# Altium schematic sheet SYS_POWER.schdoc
size 297 x 209 mm; Symbol: Drawing-Symbol_A4; Company: 嘉立创EDA; Version: V1.0; Page Size: A4; @Project Name: 西柚在学EtherCAT; @Update Date: 2026-07-29; @Create Date: 2026-07-29; Device: Drawing-Symbol_A4; @Board Name: HPM5E3YIVK1; @Page Name: P3; @Create Time: 01:19:14; @Page Count: 3; @Page No: 3; @Schematic Name: HPM5E3YIVK1; @Update Time: 01:19:14; @Assembly Variant: Basic; Border: 1; Title Block Position: 3; Size: A4; Width: 1170; Height: 825; Region Start: 1; X Region Count: 6; Y Region Count: 4; Blade Width: 10
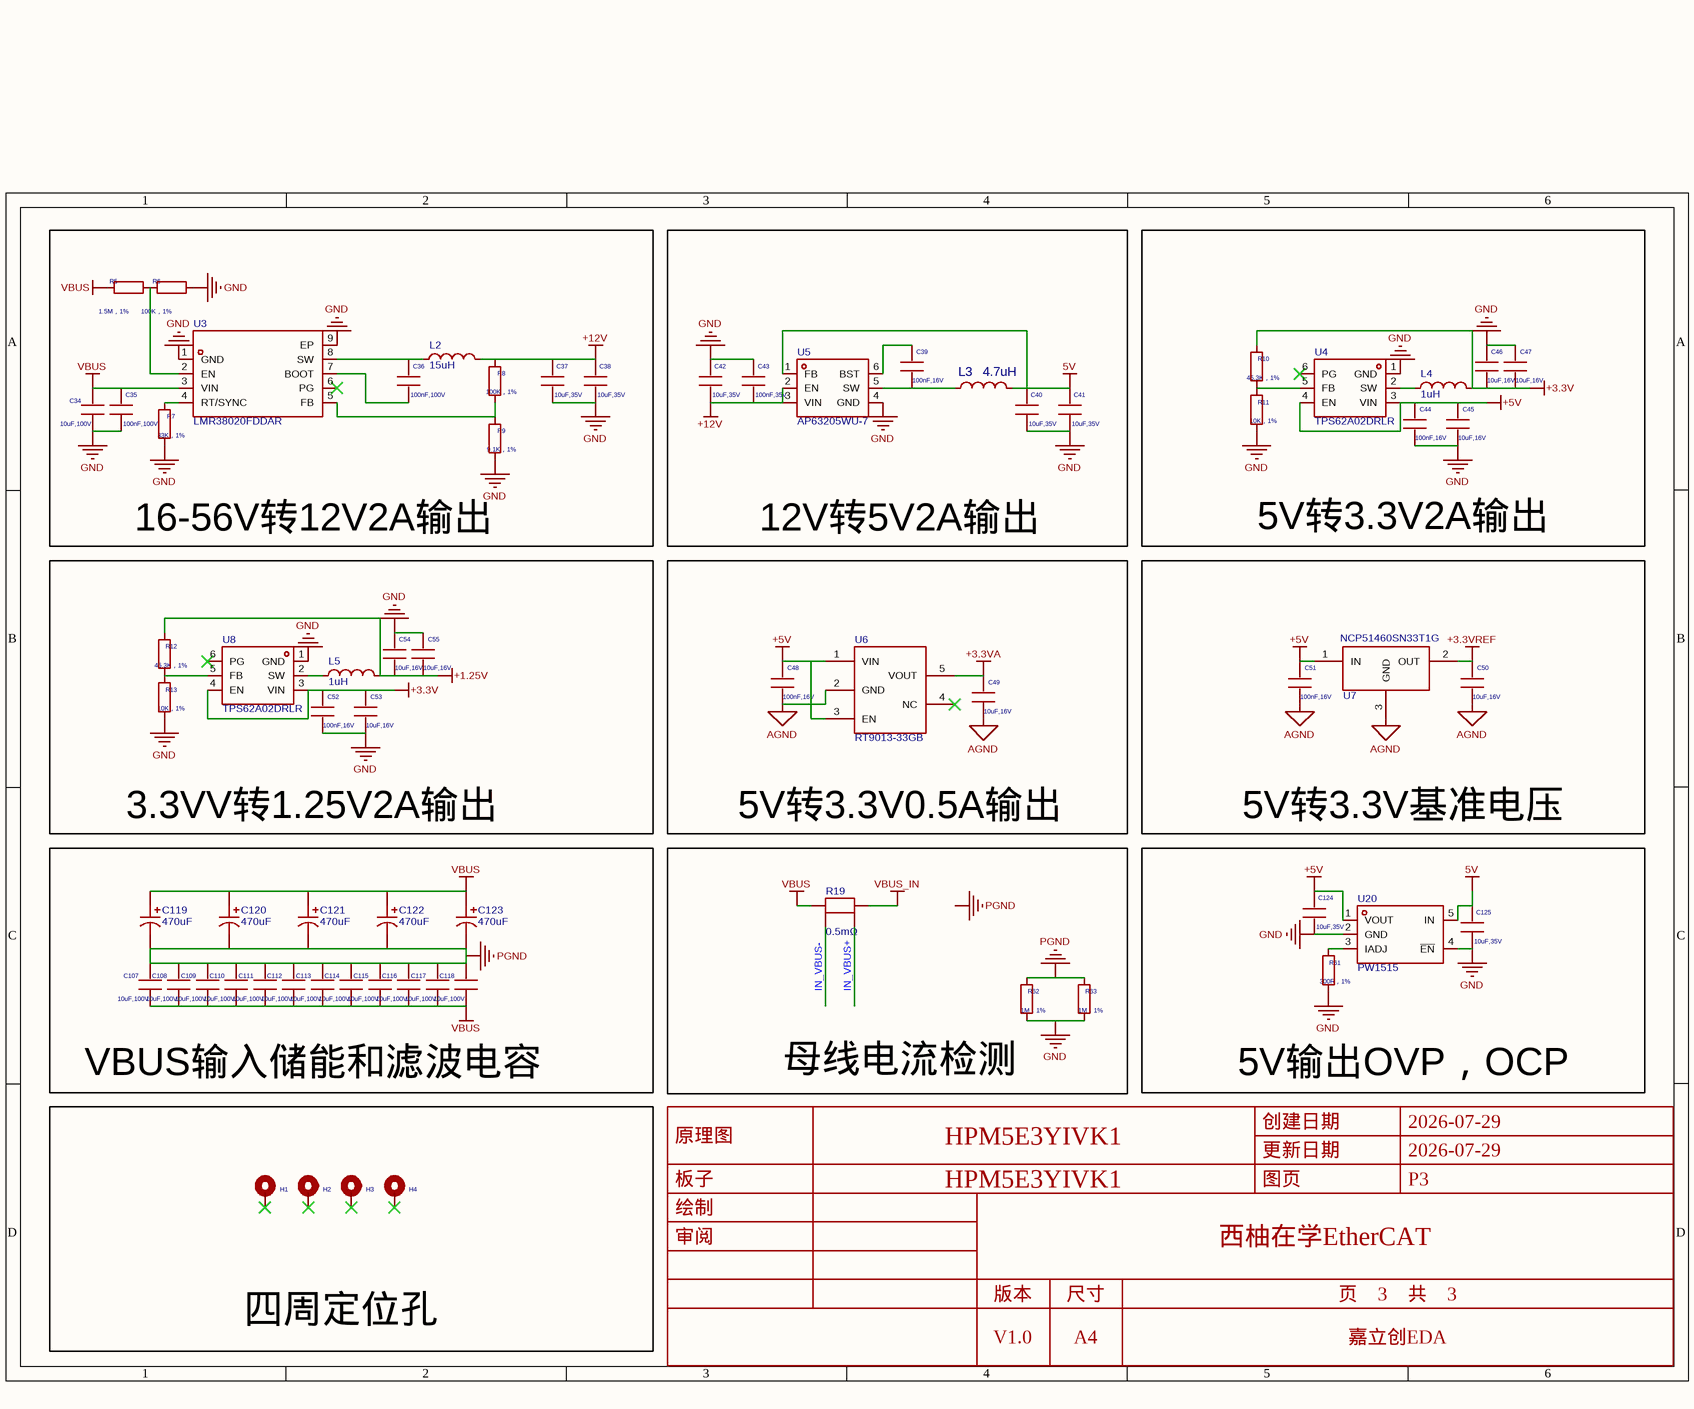
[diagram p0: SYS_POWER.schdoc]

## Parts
C34  value 10uF,100V  [03_HPM_Capacitance:C_1206_3216Metric]
C35  value 100nF,100V  [03_HPM_Capacitance:C_0603_1608Metric]
C36  value 100nF,100V  [03_HPM_Capacitance:C_0603_1608Metric]
C37  value 10uF,35V  [03_HPM_Capacitance:C_0603_1608Metric]
C38  value 10uF,35V  [03_HPM_Capacitance:C_0603_1608Metric]
C39  value 100nF,16V  [03_HPM_Capacitance:C_0402_1005Metric]
C40  value 10uF,35V  [03_HPM_Capacitance:C_0603_1608Metric]
C41  value 10uF,35V  [03_HPM_Capacitance:C_0603_1608Metric]
C42  value 10uF,35V  [03_HPM_Capacitance:C_0603_1608Metric]
C43  value 100nF,35V  [03_HPM_Capacitance:C_0603_1608Metric]
C44  value 100nF,16V  [03_HPM_Capacitance:C_0402_1005Metric]
C45  value 10uF,16V  [03_HPM_Capacitance:C_0402_1005Metric]
C46  value 10uF,16V  [03_HPM_Capacitance:C_0402_1005Metric]
C47  value 10uF,16V  [03_HPM_Capacitance:C_0402_1005Metric]
C48  value 100nF,16V  [03_HPM_Capacitance:C_0402_1005Metric]
C49  value 10uF,16V  [03_HPM_Capacitance:C_0402_1005Metric]
C50  value 10uF,16V  [03_HPM_Capacitance:C_0402_1005Metric]
C51  value 100nF,16V  [03_HPM_Capacitance:C_0402_1005Metric]
C52  value 100nF,16V  [03_HPM_Capacitance:C_0402_1005Metric]
C53  value 10uF,16V  [03_HPM_Capacitance:C_0402_1005Metric]
C54  value 10uF,16V  [03_HPM_Capacitance:C_0402_1005Metric]
C55  value 10uF,16V  [03_HPM_Capacitance:C_0402_1005Metric]
C107  value 10uF,100V  [03_HPM_Capacitance:C_1206_3216Metric]
C108  value 10uF,100V  [03_HPM_Capacitance:C_1206_3216Metric]
C109  value 10uF,100V  [03_HPM_Capacitance:C_1206_3216Metric]
C110  value 10uF,100V  [03_HPM_Capacitance:C_1206_3216Metric]
C111  value 10uF,100V  [03_HPM_Capacitance:C_1206_3216Metric]
C112  value 10uF,100V  [03_HPM_Capacitance:C_1206_3216Metric]
C113  value 10uF,100V  [03_HPM_Capacitance:C_1206_3216Metric]
C114  value 10uF,100V  [03_HPM_Capacitance:C_1206_3216Metric]
C115  value 10uF,100V  [03_HPM_Capacitance:C_1206_3216Metric]
C116  value 10uF,100V  [03_HPM_Capacitance:C_1206_3216Metric]
C117  value 10uF,100V  [03_HPM_Capacitance:C_1206_3216Metric]
C118  value 10uF,100V  [03_HPM_Capacitance:C_1206_3216Metric]
C119  470uF  [CAP-TH_BD8.0-P3.50-D0.6-FD]
C120  470uF  [CAP-TH_BD8.0-P3.50-D0.6-FD]
C121  470uF  [CAP-TH_BD8.0-P3.50-D0.6-FD]
C122  470uF  [CAP-TH_BD8.0-P3.50-D0.6-FD]
C123  470uF  [CAP-TH_BD8.0-P3.50-D0.6-FD]
C124  value 10uF,35V  [03_HPM_Capacitance:C_0603_1608Metric]
C125  value 10uF,35V  [03_HPM_Capacitance:C_0603_1608Metric]
H1  01-HPM-Peripheral_MountingHole_Pad  [01_HPM_Peripheral:FIX1]  (value not drawn)
H2  01-HPM-Peripheral_MountingHole_Pad  [01_HPM_Peripheral:FIX1]  (value not drawn)
H3  01-HPM-Peripheral_MountingHole_Pad  [01_HPM_Peripheral:FIX1]  (value not drawn)
H4  01-HPM-Peripheral_MountingHole_Pad  [01_HPM_Peripheral:FIX1]  (value not drawn)
L2  15uH  [IND-SMD_L4.6-W4.2_SMMS0420]
L3  4.7uH  [IND-SMD_L2.5-W2.0-VLS252012CX-150M]
L4  1uH  [IND-SMD_L2.5-W2.0-VLS252012CX-150M]
L5  1uH  [IND-SMD_L2.5-W2.0-VLS252012CX-150M]
R5  value 1.5M，1%  [02_HPM_Resistor:R_0402_1005Metric]
R6  value 100K，1%  [02_HPM_Resistor:R_0402_1005Metric]
R7  value 33K，1%  [02_HPM_Resistor:R_0402_1005Metric]
R8  value 100K，1%  [02_HPM_Resistor:R_0402_1005Metric]
R9  value 9.1K，1%  [02_HPM_Resistor:R_0402_1005Metric]
R10  value 45.3K，1%  [02_HPM_Resistor:R_0402_1005Metric]
R11  value 10K，1%  [02_HPM_Resistor:R_0402_1005Metric]
R12  value 45.3K，1%  [02_HPM_Resistor:R_0402_1005Metric]
R13  value 10K，1%  [02_HPM_Resistor:R_0402_1005Metric]
R19  0.5mΩ  [RES-SMD_4P-L3.0-W3.8_HOBB1216]
R61  value 300R，1%  [02_HPM_Resistor:R_0402_1005Metric]
R62  value 1M，1%  [02_HPM_Resistor:R_1206_3216Metric]
R63  value 1M，1%  [02_HPM_Resistor:R_1206_3216Metric]
U3  LMR38020FDDAR  [ESOP-8_L4.9-W3.9-P1.27-LS6.0-BL-EP-1]
U4  TPS62A02DRLR  [SOT-563_L1.6-W1.2-P0.50-LS1.6-TL]
U5  AP63205WU-7  [TSOT-23-6_L2.9-W1.6-P0.95-LS2.8-BL]
U6  RT9013-33GB  [SOT-23-5_L3.0-W1.7-P0.95-LS2.8-BL]
U7  NCP51460SN33T1G  [SOT-23_L2.9-W1.3-P1.90-LS2.4-BR]
U8  TPS62A02DRLR  [SOT-563_L1.6-W1.2-P0.50-LS1.6-TL]
U20  (no value)  [SOT-23-5_L2.9-W1.7-P0.95-LS2.8-BL]

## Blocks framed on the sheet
16-56V转12V2A输出: C34-C38 L2 R5-R9 U3
12V转5V2A输出: C39-C43 L3 U5
5V转3.3V2A输出: C44-C47 L4 R10 R11 U4
5V转3.3V基准电压: C50 C51 U7
四周定位孔: H1-H4

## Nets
5V: C40.1 C41.1 C125.1 L3.2 U5.1(FB) U20.5(IN)
+1.25V: C54.2 C55.2 L5.2 R12.1
+3.3V: C46.2 C47.2 C52.1 C53.1 L4.2 R10.1 U8.3(VIN) U8.4(EN)
+3.3VA: C49.1 U6.5(VOUT)
+3.3VREF: C50.1 U7.2(OUT)
+5V: C44.1 C45.1 C48.1 C51.1 C124.1 U4.3(VIN) U4.4(EN) U6.1(VIN) U6.3(EN) U7.1(IN) U20.1(VOUT)
+12V: C37.1 C38.1 C42.2 C43.2 L2.2 R8.2 U5.2(EN) U5.3(VIN)
AGND: C48.2 C49.2 C50.2 C51.2 U6.2(GND) U7.3(GND)
GND: C34.2 C35.2 C37.2 C38.2 C40.2 C41.2 C42.1 C43.1 C44.2 C45.2 C46.1 C47.1 C52.2 C53.2 C54.1 C55.1 C124.2 C125.2 R6.2 R7.2 R9.1 R11.1 R13.1 R61.2 R62.2 R63.2 U3.1(GND) U3.9(EP) U4.1(GND) U5.4(GND) U8.1(GND) U20.2(GND) U20.4(~{EN})
PGND: C107.1 C108.1 C109.1 C110.1 C111.1 C112.1 C113.1 C114.1 C115.1 C116.1 C117.1 C118.1 C119.2 C120.2 C121.2 C122.2 C123.2 R62.1 R63.1
VBUS: C34.1 C35.1 C107.2 C108.2 C109.2 C110.2 C111.2 C112.2 C113.2 C114.2 C115.2 C116.2 C117.2 C118.2 C119.1 C120.1 C121.1 C122.1 C123.1 R5.1 R19.2 U3.3(VIN)
VBUS_IN: R19.1
IN_VBUS+: R19.3
IN_VBUS-: R19.4
NetC36_1: C36.1 L2.1 U3.8(SW)
NetC36_2: C36.2 U3.7(BOOT)
NetC39_1: C39.1 U5.6(BST)
NetC39_2: C39.2 L3.1 U5.5(SW)
NetL4_1: L4.1 U4.2(SW)
NetL5_1: L5.1 U8.2(SW)
NetR5_2: R5.2 R6.1 U3.2(EN)
NetR7_1: R7.1 U3.4(RT/SYNC)
NetR8_1: R8.1 R9.2 U3.5(FB)
NetR10_2: R10.2 R11.2 U4.5(FB)
NetR12_2: R12.2 R13.2 U8.5(FB)
NetR61_1: R61.1 U20.3(IADJ)

Not connected (* = marked no-connect by the designer): H1 1*; H2 1*; H3 1*; H4 1*; U3 6(PG)*; U4 6(PG)*; U6 4(NC)*; U8 6(PG)*

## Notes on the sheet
- 3.3VV转1.25V2A输出
- 5V转3.3V0.5A输出
- VBUS输入储能和滤波电容
- 母线电流检测
- 5V输出OVP，OCP
- Labels drawn without touching a wire or pin: PGND

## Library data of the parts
C34 = 电容1206: Model: 1206B102K202NT; Company: FH(风华); AddInBom: yes; ki_keywords: cap capacitor; ki_description: 1206; ki_fp_filters: C_*; UniqueId: gge1041; ID: $4I70; ModelId: e4be705b945545a48e666415e3682bd80819f05c4eef4c71ace90d822a990e87; ModelName: C1206_L3.2-W1.6-H1.3; ModelTransform: 125.98400187730789,62.992000938653945,51.1809981226921,0,0,0,0,0,0
C35 = 电容0603: Model: CL10A226MP8NUNE; Company: SAMSUNG(三星); AddInBom: yes; ki_keywords: cap capacitor; ki_description: 0603; ki_fp_filters: C_*; UniqueId: gge1042; ID: $1I15; ModelId: fca5be93b99f4b5a9a2fd372d58c31d90819f05c4eef4c71ace90d822a990e87; ModelName: C0603; ModelTransform: 62.992000938653945,31.496000469326972,31.496000469326972,0,0,0,0,0,0
C36 = 电容0603: Model: CL10A226MP8NUNE; Company: SAMSUNG(三星); AddInBom: yes; ki_keywords: cap capacitor; ki_description: 0603; ki_fp_filters: C_*; UniqueId: b3e980a047527b8f_28; ID: $1I15; ModelId: fca5be93b99f4b5a9a2fd372d58c31d90819f05c4eef4c71ace90d822a990e87; ModelName: C0603; ModelTransform: 62.992000938653945,31.496000469326972,31.496000469326972,0,0,0,0,0,0
C37 = 电容0603: Model: CL10A226MP8NUNE; Company: SAMSUNG(三星); AddInBom: yes; ki_keywords: cap capacitor; ki_description: 0603; ki_fp_filters: C_*; UniqueId: b3e980a047527b8f_26; ID: $1I15; ModelId: fca5be93b99f4b5a9a2fd372d58c31d90819f05c4eef4c71ace90d822a990e87; ModelName: C0603; ModelTransform: 62.992000938653945,31.496000469326972,31.496000469326972,0,0,0,0,0,0
C38 = 电容0603: Model: CL10A226MP8NUNE; Company: SAMSUNG(三星); AddInBom: yes; ki_keywords: cap capacitor; ki_description: 0603; ki_fp_filters: C_*; UniqueId: b3e980a047527b8f_27; ID: $1I15; ModelId: fca5be93b99f4b5a9a2fd372d58c31d90819f05c4eef4c71ace90d822a990e87; ModelName: C0603; ModelTransform: 62.992000938653945,31.496000469326972,31.496000469326972,0,0,0,0,0,0
C39 = 电容0402: Model: CL05B104KO5NNNC; Company: SAMSUNG(三星); ki_keywords: cap capacitor; ki_description: 0402; ki_fp_filters: C_*; ID: $1I27; 3D Model: 222a10e09e6e477a9f85628e277082cb0819f05c4eef4c71ace90d822a990e87; 3D Model Transform: 39.37,19.685,19.685,0,0,0,0,0,0; AddInBom: yes; UniqueId: gge1020; ModelName: C0402
C40 = 电容0603: Model: CL10A226MP8NUNE; Company: SAMSUNG(三星); AddInBom: yes; ki_keywords: cap capacitor; ki_description: 0603; ki_fp_filters: C_*; UniqueId: b3e980a047527b8f_29; ID: $1I15; ModelId: fca5be93b99f4b5a9a2fd372d58c31d90819f05c4eef4c71ace90d822a990e87; ModelName: C0603; ModelTransform: 62.992000938653945,31.496000469326972,31.496000469326972,0,0,0,0,0,0
C41 = 电容0603: Model: CL10A226MP8NUNE; Company: SAMSUNG(三星); AddInBom: yes; ki_keywords: cap capacitor; ki_description: 0603; ki_fp_filters: C_*; UniqueId: b3e980a047527b8f_30; ID: $1I15; ModelId: fca5be93b99f4b5a9a2fd372d58c31d90819f05c4eef4c71ace90d822a990e87; ModelName: C0603; ModelTransform: 62.992000938653945,31.496000469326972,31.496000469326972,0,0,0,0,0,0
C42 = 电容0603: Model: CL10A226MP8NUNE; Company: SAMSUNG(三星); AddInBom: yes; ki_keywords: cap capacitor; ki_description: 0603; ki_fp_filters: C_*; UniqueId: b3e980a047527b8f_31; ID: $1I15; ModelId: fca5be93b99f4b5a9a2fd372d58c31d90819f05c4eef4c71ace90d822a990e87; ModelName: C0603; ModelTransform: 62.992000938653945,31.496000469326972,31.496000469326972,0,0,0,0,0,0
C43 = 电容0603: Model: CL10A226MP8NUNE; Company: SAMSUNG(三星); AddInBom: yes; ki_keywords: cap capacitor; ki_description: 0603; ki_fp_filters: C_*; UniqueId: b3e980a047527b8f_32; ID: $1I15; ModelId: fca5be93b99f4b5a9a2fd372d58c31d90819f05c4eef4c71ace90d822a990e87; ModelName: C0603; ModelTransform: 62.992000938653945,31.496000469326972,31.496000469326972,0,0,0,0,0,0
C44 = 电容0402: Model: CL05B104KO5NNNC; Company: SAMSUNG(三星); ki_keywords: cap capacitor; ki_description: 0402; ki_fp_filters: C_*; ID: $1I27; 3D Model: 222a10e09e6e477a9f85628e277082cb0819f05c4eef4c71ace90d822a990e87; 3D Model Transform: 39.37,19.685,19.685,0,0,0,0,0,0; AddInBom: yes; UniqueId: gge1023; ModelName: C0402
C45 = 电容0402: Model: CL05B104KO5NNNC; Company: SAMSUNG(三星); ki_keywords: cap capacitor; ki_description: 0402; ki_fp_filters: C_*; ID: $1I27; 3D Model: 222a10e09e6e477a9f85628e277082cb0819f05c4eef4c71ace90d822a990e87; 3D Model Transform: 39.37,19.685,19.685,0,0,0,0,0,0; AddInBom: yes; UniqueId: gge1024; ModelName: C0402
C46 = 电容0402: Model: CL05B104KO5NNNC; Company: SAMSUNG(三星); ki_keywords: cap capacitor; ki_description: 0402; ki_fp_filters: C_*; ID: $1I27; 3D Model: 222a10e09e6e477a9f85628e277082cb0819f05c4eef4c71ace90d822a990e87; 3D Model Transform: 39.37,19.685,19.685,0,0,0,0,0,0; AddInBom: yes; UniqueId: b3e980a047527b8f_33; ModelName: C0402
C47 = 电容0402: Model: CL05B104KO5NNNC; Company: SAMSUNG(三星); ki_keywords: cap capacitor; ki_description: 0402; ki_fp_filters: C_*; ID: $1I27; 3D Model: 222a10e09e6e477a9f85628e277082cb0819f05c4eef4c71ace90d822a990e87; 3D Model Transform: 39.37,19.685,19.685,0,0,0,0,0,0; AddInBom: yes; UniqueId: b3e980a047527b8f_34; ModelName: C0402
C48 = 电容0402: Model: CL05B104KO5NNNC; Company: SAMSUNG(三星); ki_keywords: cap capacitor; ki_description: 0402; ki_fp_filters: C_*; ID: $1I27; 3D Model: 222a10e09e6e477a9f85628e277082cb0819f05c4eef4c71ace90d822a990e87; 3D Model Transform: 39.37,19.685,19.685,0,0,0,0,0,0; AddInBom: yes; UniqueId: b3e980a047527b8f_35; ModelName: C0402
C49 = 电容0402: Model: CL05B104KO5NNNC; Company: SAMSUNG(三星); ki_keywords: cap capacitor; ki_description: 0402; ki_fp_filters: C_*; ID: $1I27; 3D Model: 222a10e09e6e477a9f85628e277082cb0819f05c4eef4c71ace90d822a990e87; 3D Model Transform: 39.37,19.685,19.685,0,0,0,0,0,0; AddInBom: yes; UniqueId: b3e980a047527b8f_36; ModelName: C0402
C50 = 电容0402: Model: CL05B104KO5NNNC; Company: SAMSUNG(三星); ki_keywords: cap capacitor; ki_description: 0402; ki_fp_filters: C_*; ID: $1I27; 3D Model: 222a10e09e6e477a9f85628e277082cb0819f05c4eef4c71ace90d822a990e87; 3D Model Transform: 39.37,19.685,19.685,0,0,0,0,0,0; AddInBom: yes; UniqueId: b3e980a047527b8f_37; ModelName: C0402
C51 = 电容0402: Model: CL05B104KO5NNNC; Company: SAMSUNG(三星); ki_keywords: cap capacitor; ki_description: 0402; ki_fp_filters: C_*; ID: $1I27; 3D Model: 222a10e09e6e477a9f85628e277082cb0819f05c4eef4c71ace90d822a990e87; 3D Model Transform: 39.37,19.685,19.685,0,0,0,0,0,0; AddInBom: yes; UniqueId: b3e980a047527b8f_38; ModelName: C0402
C52 = 电容0402: Model: CL05B104KO5NNNC; Company: SAMSUNG(三星); ki_keywords: cap capacitor; ki_description: 0402; ki_fp_filters: C_*; ID: $1I27; 3D Model: 222a10e09e6e477a9f85628e277082cb0819f05c4eef4c71ace90d822a990e87; 3D Model Transform: 39.37,19.685,19.685,0,0,0,0,0,0; AddInBom: yes; UniqueId: gge1023_0; ModelName: C0402
C53 = 电容0402: Model: CL05B104KO5NNNC; Company: SAMSUNG(三星); ki_keywords: cap capacitor; ki_description: 0402; ki_fp_filters: C_*; ID: $1I27; 3D Model: 222a10e09e6e477a9f85628e277082cb0819f05c4eef4c71ace90d822a990e87; 3D Model Transform: 39.37,19.685,19.685,0,0,0,0,0,0; AddInBom: yes; UniqueId: gge1024_0; ModelName: C0402
C54 = 电容0402: Model: CL05B104KO5NNNC; Company: SAMSUNG(三星); ki_keywords: cap capacitor; ki_description: 0402; ki_fp_filters: C_*; ID: $1I27; 3D Model: 222a10e09e6e477a9f85628e277082cb0819f05c4eef4c71ace90d822a990e87; 3D Model Transform: 39.37,19.685,19.685,0,0,0,0,0,0; AddInBom: yes; UniqueId: b3e980a047527b8f_39; ModelName: C0402
C55 = 电容0402: Model: CL05B104KO5NNNC; Company: SAMSUNG(三星); ki_keywords: cap capacitor; ki_description: 0402; ki_fp_filters: C_*; ID: $1I27; 3D Model: 222a10e09e6e477a9f85628e277082cb0819f05c4eef4c71ace90d822a990e87; 3D Model Transform: 39.37,19.685,19.685,0,0,0,0,0,0; AddInBom: yes; UniqueId: b3e980a047527b8f_40; ModelName: C0402
C107 = 电容1206: Model: 1206B102K202NT; Company: FH(风华); ki_keywords: cap capacitor; ki_description: 1206; ki_fp_filters: C_*; ID: $4I70; 3D Model: e4be705b945545a48e666415e3682bd80819f05c4eef4c71ace90d822a990e87; 3D Model Transform: 125.98400187730789,62.992000938653945,51.1809981226921,0,0,0,0,0,0; AddInBom: yes; UniqueId: gge1041_0; ModelName: C1206_L3.2-W1.6-H1.3
C108 = 电容1206: Model: 1206B102K202NT; Company: FH(风华); ki_keywords: cap capacitor; ki_description: 1206; ki_fp_filters: C_*; ID: $4I70; 3D Model: e4be705b945545a48e666415e3682bd80819f05c4eef4c71ace90d822a990e87; 3D Model Transform: 125.98400187730789,62.992000938653945,51.1809981226921,0,0,0,0,0,0; AddInBom: yes; UniqueId: gge1041_1; ModelName: C1206_L3.2-W1.6-H1.3
C109 = 电容1206: Model: 1206B102K202NT; Company: FH(风华); ki_keywords: cap capacitor; ki_description: 1206; ki_fp_filters: C_*; ID: $4I70; 3D Model: e4be705b945545a48e666415e3682bd80819f05c4eef4c71ace90d822a990e87; 3D Model Transform: 125.98400187730789,62.992000938653945,51.1809981226921,0,0,0,0,0,0; AddInBom: yes; UniqueId: gge1041_2; ModelName: C1206_L3.2-W1.6-H1.3
C110 = 电容1206: Model: 1206B102K202NT; Company: FH(风华); ki_keywords: cap capacitor; ki_description: 1206; ki_fp_filters: C_*; ID: $4I70; 3D Model: e4be705b945545a48e666415e3682bd80819f05c4eef4c71ace90d822a990e87; 3D Model Transform: 125.98400187730789,62.992000938653945,51.1809981226921,0,0,0,0,0,0; AddInBom: yes; UniqueId: gge1041_3; ModelName: C1206_L3.2-W1.6-H1.3
C111 = 电容1206: Model: 1206B102K202NT; Company: FH(风华); ki_keywords: cap capacitor; ki_description: 1206; ki_fp_filters: C_*; ID: $4I70; 3D Model: e4be705b945545a48e666415e3682bd80819f05c4eef4c71ace90d822a990e87; 3D Model Transform: 125.98400187730789,62.992000938653945,51.1809981226921,0,0,0,0,0,0; AddInBom: yes; UniqueId: gge1041_8; ModelName: C1206_L3.2-W1.6-H1.3
C112 = 电容1206: Model: 1206B102K202NT; Company: FH(风华); ki_keywords: cap capacitor; ki_description: 1206; ki_fp_filters: C_*; ID: $4I70; 3D Model: e4be705b945545a48e666415e3682bd80819f05c4eef4c71ace90d822a990e87; 3D Model Transform: 125.98400187730789,62.992000938653945,51.1809981226921,0,0,0,0,0,0; AddInBom: yes; UniqueId: gge1041_9; ModelName: C1206_L3.2-W1.6-H1.3
C113 = 电容1206: Model: 1206B102K202NT; Company: FH(风华); ki_keywords: cap capacitor; ki_description: 1206; ki_fp_filters: C_*; ID: $4I70; 3D Model: e4be705b945545a48e666415e3682bd80819f05c4eef4c71ace90d822a990e87; 3D Model Transform: 125.98400187730789,62.992000938653945,51.1809981226921,0,0,0,0,0,0; AddInBom: yes; UniqueId: gge1041_12; ModelName: C1206_L3.2-W1.6-H1.3
C114 = 电容1206: Model: 1206B102K202NT; Company: FH(风华); ki_keywords: cap capacitor; ki_description: 1206; ki_fp_filters: C_*; ID: $4I70; 3D Model: e4be705b945545a48e666415e3682bd80819f05c4eef4c71ace90d822a990e87; 3D Model Transform: 125.98400187730789,62.992000938653945,51.1809981226921,0,0,0,0,0,0; AddInBom: yes; UniqueId: gge1041_7; ModelName: C1206_L3.2-W1.6-H1.3
C115 = 电容1206: Model: 1206B102K202NT; Company: FH(风华); ki_keywords: cap capacitor; ki_description: 1206; ki_fp_filters: C_*; ID: $4I70; 3D Model: e4be705b945545a48e666415e3682bd80819f05c4eef4c71ace90d822a990e87; 3D Model Transform: 125.98400187730789,62.992000938653945,51.1809981226921,0,0,0,0,0,0; AddInBom: yes; UniqueId: gge1041_4; ModelName: C1206_L3.2-W1.6-H1.3
C116 = 电容1206: Model: 1206B102K202NT; Company: FH(风华); ki_keywords: cap capacitor; ki_description: 1206; ki_fp_filters: C_*; ID: $4I70; 3D Model: e4be705b945545a48e666415e3682bd80819f05c4eef4c71ace90d822a990e87; 3D Model Transform: 125.98400187730789,62.992000938653945,51.1809981226921,0,0,0,0,0,0; AddInBom: yes; UniqueId: gge1041_5; ModelName: C1206_L3.2-W1.6-H1.3
C117 = 电容1206: Model: 1206B102K202NT; Company: FH(风华); ki_keywords: cap capacitor; ki_description: 1206; ki_fp_filters: C_*; ID: $4I70; 3D Model: e4be705b945545a48e666415e3682bd80819f05c4eef4c71ace90d822a990e87; 3D Model Transform: 125.98400187730789,62.992000938653945,51.1809981226921,0,0,0,0,0,0; AddInBom: yes; UniqueId: gge1041_10; ModelName: C1206_L3.2-W1.6-H1.3
C118 = 电容1206: Model: 1206B102K202NT; Company: FH(风华); ki_keywords: cap capacitor; ki_description: 1206; ki_fp_filters: C_*; ID: $4I70; 3D Model: e4be705b945545a48e666415e3682bd80819f05c4eef4c71ace90d822a990e87; 3D Model Transform: 125.98400187730789,62.992000938653945,51.1809981226921,0,0,0,0,0,0; AddInBom: yes; UniqueId: gge1041_11; ModelName: C1206_L3.2-W1.6-H1.3
C119-C123 = BC025M471LO8*12L-1A4T: 容值:470uF;精度:±20%;额定电压:25V;纹波电流:4.1A@100kHz;等效串联电阻(ESR):20mΩ@100kHz;类型:-;; Manufacturer: BERYL(绿宝石); AddInBom: yes; ModelId: a2c936ec27754f809f3966430e36f7670819f05c4eef4c71ace90d822a990e87; ModelName: CAP-TH_D8.0-H8.0-P3.50; ModelTransform: 314.96,314.862,0,180,0,0,0,0,-137.795; Tolerance: ±20%; Voltage Rating: 25V; Pin Spacing: 3.5mm; Lifetime: 2000hrs@105℃
C124 = 电容0603: Model: CL10A226MP8NUNE; Company: SAMSUNG(三星); ki_keywords: cap capacitor; ki_description: 0603; ki_fp_filters: C_*; ID: $1I15; 3D Model: fca5be93b99f4b5a9a2fd372d58c31d90819f05c4eef4c71ace90d822a990e87; 3D Model Transform: 62.992000938653945,31.496000469326972,31.496000469326972,0,0,0,0,0,0; AddInBom: yes; UniqueId: b3e980a047527b8f_52; ModelName: C0603
C125 = 电容0603: Model: CL10A226MP8NUNE; Company: SAMSUNG(三星); ki_keywords: cap capacitor; ki_description: 0603; ki_fp_filters: C_*; ID: $1I15; 3D Model: fca5be93b99f4b5a9a2fd372d58c31d90819f05c4eef4c71ace90d822a990e87; 3D Model Transform: 62.992000938653945,31.496000469326972,31.496000469326972,0,0,0,0,0,0; AddInBom: yes; UniqueId: b3e980a047527b8f_53; ModelName: C0603
H1-H4 = 01-HPM-Peripheral_MountingHole_Pad: Attribute1: H2; Sheetfile: 10.MISC.kicad_sch; Sheetname: 10.MISC; ki_description: Mounting Hole with connection; ki_fp_filters: MountingHole*Pad*; Origin Footprint: 01_HPM_Peripheral:MountingHole_3.2mm_M3_Pad; AddInBom: yes
L2 = SMMS0420-150M: 电感值:15uH;精度:±20%;额定电流:1.4A;饱和电流(Isat):1.9A;类型:-;; Manufacturer: SXN(顺翔诺); AddInBom: yes; ModelId: 632d2327aa744dee844d0b81cf3c80120819f05c4eef4c71ace90d822a990e87; ModelTransform: 181.102,165.354,0,0,0,0,0,0,0; Tolerance: ±20%; Current Rating: 1.4A; Current - Saturation(Isat): 1.9A; DC Resistance(DCR): 320mΩ
L3 = FTC252010S4R7MBCA: Manufacturer: cjiang(长江微电); Tolerance: ±20%; Rated Current: 2A; Saturation Current (Isat): 2.6A; DC Resistance (DCR): 160mΩ; Type: 一体成型电感; 3D Model: e143e04106934774881cec608355723f; 3D Model Transform: 98.504,78.819,0,0,0,0,-0.004,-0.003,0; AddInBom: yes
L4 L5 = FTC252012S1R0MBCA: 电感值:1uH;精度:±20%;额定电流:4A;饱和电流(Isat):5.6A;类型:-;; Manufacturer: cjiang(长江微电); AddInBom: yes; ModelId: e143e04106934774881cec608355723f0819f05c4eef4c71ace90d822a990e87; ModelTransform: 98.504,78.819,0,0,0,0,-0.004,-0.003,0; Tolerance: ±20%; Current Rating: 4A; Current - Saturation(Isat): 5.6A; DC Resistance(DCR): 35mΩ
R5 = 电阻0402: Model: 0402WGF1002TCE; Company: UNI-ROYAL(厚声); ki_keywords: R res resistor; ki_description: Resistor; ki_fp_filters: R_*; ID: $3I57; 3D Model: 98c88bc2b9094f218f3a3e30a70127380819f05c4eef4c71ace90d822a990e87; 3D Model Transform: 39.37,19.685,14.173200563192367,0,0,0,0,0,0; AddInBom: yes; UniqueId: gge1015; ModelName: R0402_L1.0-W0.5-H0.4
R6 = 电阻0402: Model: 0402WGF1002TCE; Company: UNI-ROYAL(厚声); ki_keywords: R res resistor; ki_description: Resistor; ki_fp_filters: R_*; ID: $3I57; 3D Model: 98c88bc2b9094f218f3a3e30a70127380819f05c4eef4c71ace90d822a990e87; 3D Model Transform: 39.37,19.685,14.173200563192367,0,0,0,0,0,0; AddInBom: yes; UniqueId: gge1016; ModelName: R0402_L1.0-W0.5-H0.4
R7 = 电阻0402: Model: 0402WGF1002TCE; Company: UNI-ROYAL(厚声); ki_keywords: R res resistor; ki_description: Resistor; ki_fp_filters: R_*; ID: $3I57; 3D Model: 98c88bc2b9094f218f3a3e30a70127380819f05c4eef4c71ace90d822a990e87; 3D Model Transform: 39.37,19.685,14.173200563192367,0,0,0,0,0,0; AddInBom: yes; UniqueId: 469542c170a520e3_3; ModelName: R0402_L1.0-W0.5-H0.4
R8 = 电阻0402: Model: 0402WGF1002TCE; Company: UNI-ROYAL(厚声); ki_keywords: R res resistor; ki_description: Resistor; ki_fp_filters: R_*; ID: $3I57; 3D Model: 98c88bc2b9094f218f3a3e30a70127380819f05c4eef4c71ace90d822a990e87; 3D Model Transform: 39.37,19.685,14.173200563192367,0,0,0,0,0,0; AddInBom: yes; UniqueId: gge1018; ModelName: R0402_L1.0-W0.5-H0.4
R9 = 电阻0402: Model: 0402WGF1002TCE; Company: UNI-ROYAL(厚声); ki_keywords: R res resistor; ki_description: Resistor; ki_fp_filters: R_*; ID: $3I57; 3D Model: 98c88bc2b9094f218f3a3e30a70127380819f05c4eef4c71ace90d822a990e87; 3D Model Transform: 39.37,19.685,14.173200563192367,0,0,0,0,0,0; AddInBom: yes; UniqueId: 469542c170a520e3_4; ModelName: R0402_L1.0-W0.5-H0.4
R10 = 电阻0402: Model: 0402WGF1002TCE; Company: UNI-ROYAL(厚声); ki_keywords: R res resistor; ki_description: Resistor; ki_fp_filters: R_*; ID: $3I57; 3D Model: 98c88bc2b9094f218f3a3e30a70127380819f05c4eef4c71ace90d822a990e87; 3D Model Transform: 39.37,19.685,14.173200563192367,0,0,0,0,0,0; AddInBom: yes; UniqueId: gge1018_0; ModelName: R0402_L1.0-W0.5-H0.4
R11 = 电阻0402: Model: 0402WGF1002TCE; Company: UNI-ROYAL(厚声); ki_keywords: R res resistor; ki_description: Resistor; ki_fp_filters: R_*; ID: $3I57; 3D Model: 98c88bc2b9094f218f3a3e30a70127380819f05c4eef4c71ace90d822a990e87; 3D Model Transform: 39.37,19.685,14.173200563192367,0,0,0,0,0,0; AddInBom: yes; UniqueId: gge1018_1; ModelName: R0402_L1.0-W0.5-H0.4
R12 = 电阻0402: Model: 0402WGF1002TCE; Company: UNI-ROYAL(厚声); ki_keywords: R res resistor; ki_description: Resistor; ki_fp_filters: R_*; ID: $3I57; 3D Model: 98c88bc2b9094f218f3a3e30a70127380819f05c4eef4c71ace90d822a990e87; 3D Model Transform: 39.37,19.685,14.173200563192367,0,0,0,0,0,0; AddInBom: yes; UniqueId: gge1018_2; ModelName: R0402_L1.0-W0.5-H0.4
R13 = 电阻0402: Model: 0402WGF1002TCE; Company: UNI-ROYAL(厚声); ki_keywords: R res resistor; ki_description: Resistor; ki_fp_filters: R_*; ID: $3I57; 3D Model: 98c88bc2b9094f218f3a3e30a70127380819f05c4eef4c71ace90d822a990e87; 3D Model Transform: 39.37,19.685,14.173200563192367,0,0,0,0,0,0; AddInBom: yes; UniqueId: gge1018_3; ModelName: R0402_L1.0-W0.5-H0.4
R19 = HoBB1216-5W-0.5mR-1%: 电阻类型:采样电阻;阻值:0.5mΩ;精度:±1%;功率:5W;温度系数:±50ppm/℃;安装方式:贴片;; Manufacturer: Milliohm(毫欧); 3D Model: 982d1509d24f4f009544b104e5e1a8a30819f05c4eef4c71ace90d822a990e87; 3D Model Transform: 118.5037,150.3934,0,180,0,0,0,-20.039,0; Tolerance: ±1%; Power(Watts): 5W; AddInBom: yes
R61 = 电阻0402: Model: 0402WGF1002TCE; Company: UNI-ROYAL(厚声); ki_keywords: R res resistor; ki_description: Resistor; ki_fp_filters: R_*; ID: $3I57; 3D Model: 98c88bc2b9094f218f3a3e30a70127380819f05c4eef4c71ace90d822a990e87; 3D Model Transform: 39.37,19.685,14.173200563192367,0,0,0,0,0,0; AddInBom: yes; UniqueId: 469542c170a520e3_41; ModelName: R0402_L1.0-W0.5-H0.4
R62 = 电阻1206: Model: ARG06BTC1004; Company: Viking(光颉); ki_keywords: R res resistor; ki_description: Resistor; ki_fp_filters: R_*; ID: $4I74; 3D Model: 89a1f13db2384da588040e0b3c55bf660819f05c4eef4c71ace90d822a990e87; 3D Model Transform: 125.98400187730789,62.992000938653945,22.047200093865392,0,0,0,0,0,0; AddInBom: yes; UniqueId: gge1033_1; ModelName: R1206_L3.2-W1.6-H0.6
R63 = 电阻1206: Model: ARG06BTC1004; Company: Viking(光颉); ki_keywords: R res resistor; ki_description: Resistor; ki_fp_filters: R_*; ID: $4I74; 3D Model: 89a1f13db2384da588040e0b3c55bf660819f05c4eef4c71ace90d822a990e87; 3D Model Transform: 125.98400187730789,62.992000938653945,22.047200093865392,0,0,0,0,0,0; AddInBom: yes; UniqueId: gge1033_2; ModelName: R1206_L3.2-W1.6-H0.6
U3 = LMR38020FDDAR: 功能类型:降压型;工作电压:4.2V~80V;输出电压:1V~75V;输出电流:2A;输出类型:可调;; Manufacturer: TI(德州仪器); AddInBom: yes; ModelId: 1edf17d9e1eb44b9aabe355eb95382d10819f05c4eef4c71ace90d822a990e87; ModelTransform: 192.913,236.22,0,0,0,0,0,0,0; Function: 降压型; Output Voltage: 1V~75V; Output Current: 2A; Frequency - Switching: 525kHz; Synchronous Rectifier: 是; Number of Outputs: 1; Topology: 降压式; Quiescent Current: 40uA; Switch tube (built-in/external): 内置; Output Type: 可调
U4 U8 = TPS62A02DRLR: 功能类型:降压型;工作电压:2.5V~5.5V;输出电压:600mV~5.5V;输出电流:2A;输出类型:可调;; Manufacturer: TI(德州仪器); 3D Model: ae4c13e967cf4f598e77975e9d61b1bf0819f05c4eef4c71ace90d822a990e87; 3D Model Transform: 62.992,62.992,0,0,0,0,-0.002,-1.144,0; Function: 降压型; Output Current: 2A; Frequency - Switching: 2.4MHz; Synchronous Rectifier: 是; Number of Outputs: 1; Topology: 降压式; Quiescent Current: 23uA; Switch tube (built-in/external): 内置; Output Type: 可调; AddInBom: yes; ModelName: SOT-563-6P_L1.6-W1.2-H0.6-LS1.6-P0.50
U5 = AP63205WU-7: 功能类型:降压型;工作电压:3.8V~32V;输出电压:5V;输出电流:2A;输出类型:固定;; Manufacturer: DIODES(美台); AddInBom: yes; ModelId: 2c4039b5b88644c1bda4b4ba9e9716670819f05c4eef4c71ace90d822a990e87; ModelName: TSOT-23-6_L2.9-W1.6-H1.1-LS2.8-P0.95; ModelTransform: 110.236,114.173,0,90,0,0,0,0,0; Function: 降压型; Output Voltage: 5V; Output Current: 2A; Frequency - Switching: 1.1MHz; Synchronous Rectifier: 是; Number of Outputs: 1; Topology: 降压式; Quiescent Current: 22uA; Switch tube (built-in/external): 内置; Output Type: 固定
U6 = RT9013-33GB: 输出极性:正极;工作电压:5.5V;输出电压:3.3V;输出电流:500mA;电源纹波抑制比(PSRR):50dB@(10kHz);输出类型:固定;; Manufacturer: RICHTEK(立锜); AddInBom: yes; ModelId: 0a2a1b8f50944f73965918ad6e5fe1670819f05c4eef4c71ace90d822a990e87; ModelName: SOT-23-5_L2.9-W1.6-H1.1-LS2.8-P0.95; ModelTransform: 118.60433,114.173,0,90,0,0,0.0005,0.0005,0; Output Configuration: 正极; Voltage - Supply: 5.5V; Output Voltage: 3.3V; Output Current: 500mA; Voltage Dropout: 400mV@(500mA); standby current: 25uA; Noise: 30uVrms; Output Type: 固定; Number of Outputs: 1
U7 = NCP51460SN33T1G: 输出类型:固定;工作电压:4.2V~28V;输出电压:3.3V;输出电流:20mA;精度:±1%;; Manufacturer: onsemi(安森美); AddInBom: yes; ModelId: c62791f0466c4ae2a892c056b845b0ca0819f05c4eef4c71ace90d822a990e87; ModelName: SOT-23-3P_L2.9-W1.3-H1.0-LS2.4-P0.95; ModelTransform: 98.64468,114.173,0,180,0,0,0.001,-0.002,0; Output Type: 固定; Output Voltage: 3.3V; Output Current: 20mA; Tolerance: ±1%; Temperature Coefficient: 18ppm/℃; Reference Type: 串联; Quiescent Current: 220uA; Noise - 1/10Hz to 10Hz: 12uVp-p; Noise - 10Hz to 10kHz: 18uVrms
U20 = PW1515: AddInBom: yes; ModelId: bc68d73ac92c4e0f9e95c23bce7b07060819f05c4eef4c71ace90d822a990e87; ModelTransform: 114.17300375461578,110.2359981226921,46.25975046932697,0,0,0,0,0,0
